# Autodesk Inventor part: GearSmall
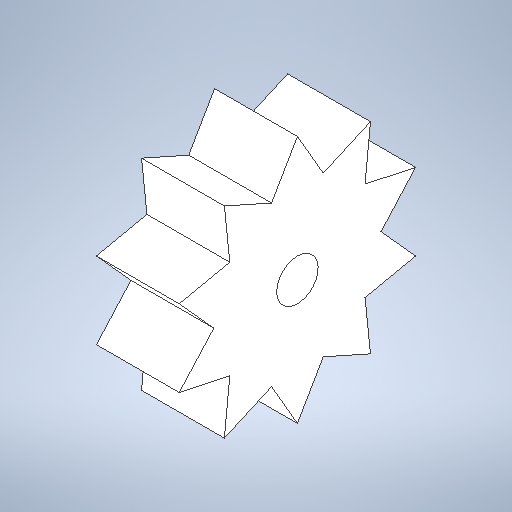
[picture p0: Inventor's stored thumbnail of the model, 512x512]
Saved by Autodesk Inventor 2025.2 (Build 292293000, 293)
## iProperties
Created: 2025-09
Part Number: GearSmall
Material: Generic
Document SubType Name: Modeling
Designer: tyler
Density: 1 g/cm^3
Appearance: Default
Author: tyler
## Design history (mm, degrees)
sketch "Sketch1"
  geometry: L1 (6.35, 0)-(9.525, 0); L2 (9.525, 0)-(6.019, -2.024); L3 (9.525, 0)-(6.019, 2.024); L4 (9.525, 0)-(13.574, 0); L5 (7.706, 5.599)-(3.679, 5.175); L6 (7.706, 5.599)-(6.059, 1.9); L7 (2.943, 9.059)-(-0.065, 6.35); L8 (2.943, 9.059)-(3.785, 5.099); L9 (-2.943, 9.059)-(-3.785, 5.099); L10 (-2.943, 9.059)-(0.065, 6.35); L11 (-7.706, 5.599)-(-6.059, 1.9); L12 (-7.706, 5.599)-(-3.679, 5.175); L13 (-9.525, 0)-(-6.019, -2.024); L14 (-9.525, 0)-(-6.019, 2.024); L15 (-7.706, -5.599)-(-3.679, -5.175); L16 (-7.706, -5.599)-(-6.059, -1.9); L17 (-2.943, -9.059)-(0.065, -6.35); L18 (-2.943, -9.059)-(-3.785, -5.099); L19 (2.943, -9.059)-(3.785, -5.099); L20 (2.943, -9.059)-(-0.065, -6.35); L21 (7.706, -5.599)-(6.059, -1.9); L22 (7.706, -5.599)-(3.679, -5.175); C1 r 1.587 at (0, 0); A1 r 6.35 centre (0, 0) between (6.35, 0) and (6.019, -2.024); 11 further points
  constraints: 44 end point, 3 point on circle, 2 centre point, 2 coincident, 2 horizontal, 1 equal length, 51 other
  dimensions: "d0" = 12.7 diameter of A1; "d1" = 3.175 diameter of C1; "d2" = 3.175 distance of L1.start L1.end; "d3" = 30 deg angle of L1 L2; "d4" = 150 deg angle of L4 L3; "d7" = 360 deg dimension on point (0, 0) L1.end (derived)
extrude "Extrusion1" new body sketch "Sketch1" distance "d9" = 6.35; taper "d10" = 0 deg
body "Solid1"
node "Sketch Circular Pattern1" dims "d7" = 360 deg (derived)
